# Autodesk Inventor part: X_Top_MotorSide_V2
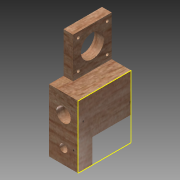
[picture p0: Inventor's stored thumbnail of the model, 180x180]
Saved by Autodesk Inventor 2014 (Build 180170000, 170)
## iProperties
Created: 2013-12
Part Number: X_Top_MotorSide_V2
Material: Birch
Document SubType Name: Modeling
Designer: Bram
Density: 0.512 g/cm^3
Appearance: Birch - Natural Medium Gloss
Author: Bram
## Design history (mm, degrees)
sketch "Sketch1"
  geometry: L1 (0, 0)-(30, 0); L2 (30, 0)-(30, 107); L3 (30, 107)-(0, 107); L4 (0, 107)-(0, 0); L5 (0, 107)-(20, 107); L6 (20, 107)-(20, 65); L7 (20, 65)-(0, 65); L8 (0, 65)-(0, 107); C1 r 4 at (15, 15); C2 r 7.5 at (15, 45)
  constraints: 16 end point, 4 parallel, 2 centre point, 2 horizontal, 2 perpendicular
  dimensions: "d0" = 30 distance of L3.end L2.end; "d1" = 107 distance of L2.end L1.end; "d2" = 20 distance of L6.end L7.end; "d3" = 42 distance of L5.end L6.end; "d6" = 8 diameter of C1; "d7" = 15 diameter of C2
extrude "Extrusion1" new body sketch "Sketch1" distance "d8" = 55; taper "d9" = 0 deg
sketch "Sketch2"
  geometry: L1 (0, 55)-(0, 0) reference; L2 (0, 0)-(65, 0) reference; L3 (65, 0)-(65, 55) reference; L4 (0, 55)-(65, 55) reference
sketch "Sketch3"
  geometry: L1 (-42, 0)-(0, 0); L2 (0, 0)-(0, 15); L3 (0, 15)-(-42, 15); L4 (-42, 15)-(-42, 0); C1 r 12 at (-22, 35); C2 r 1.5 at (-36.5, 50.5); C3 r 1.5 at (-6.5, 50.5); C4 r 1.5 at (-6.5, 20.5); C5 r 1.5 at (-36.5, 20.5); 1 further point
  constraints: 8 end point, 5 centre point, 2 parallel, 1 horizontal, 1 perpendicular
  dimensions: "d12" = 24 diameter of C1; "d18" = 3 diameter of C2; "d19" = 3 diameter of C3; "d20" = 3 diameter of C4; "d21" = 3 diameter of C5; "d22" = 42 distance of L3.end L2.end; "d23" = 15 distance of L2.end L1.end
extrude "Extrusion2" cut sketch "Sketch3" distance "d24" = 55; taper "d25" = 0 deg
sketch "Sketch4"
  geometry: L1 (65, 55)-(40, 55); L2 (40, 55)-(40, 15); L3 (40, 15)-(65, 15); L4 (65, 15)-(65, 55)
  constraints: 8 end point, 2 parallel, 1 horizontal, 1 perpendicular
  dimensions: "d26" = 25 distance of L3.end L2.end; "d27" = 40 distance of L2.end L1.end
extrude "Extrusion3" cut sketch "Sketch4" distance "d28" = 55; taper "d29" = 0 deg
body "Solid1"
